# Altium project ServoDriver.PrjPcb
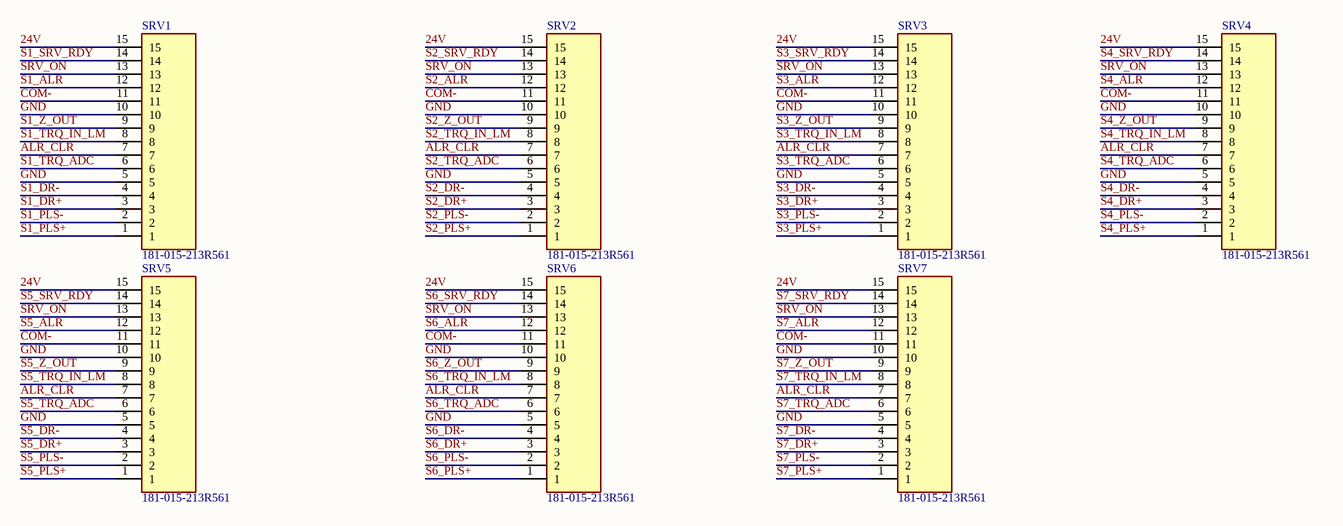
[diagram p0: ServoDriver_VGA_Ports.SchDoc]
1 sheet, 7 parts. Net scope: global (net labels, ports and power ports of the same name join across sheets).
Board file: ServoDriver.PcbDoc

## Sheet ServoDriver_VGA_Ports.SchDoc
size A4

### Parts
SRV1  181-015-213R561  [NORCOMP_181-015-213R561]
SRV2  181-015-213R561  [NORCOMP_181-015-213R561]
SRV3  181-015-213R561  [NORCOMP_181-015-213R561]
SRV4  181-015-213R561  [NORCOMP_181-015-213R561]
SRV5  181-015-213R561  [NORCOMP_181-015-213R561]
SRV6  181-015-213R561  [NORCOMP_181-015-213R561]
SRV7  181-015-213R561  [NORCOMP_181-015-213R561]

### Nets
24V: SRV1.15 SRV2.15 SRV3.15 SRV4.15 SRV5.15 SRV6.15 SRV7.15
ALR_CLR: SRV1.7 SRV2.7 SRV3.7 SRV4.7 SRV5.7 SRV6.7 SRV7.7
COM-: SRV1.11 SRV2.11 SRV3.11 SRV4.11 SRV5.11 SRV6.11 SRV7.11
GND: SRV1.5 SRV1.10 SRV2.5 SRV2.10 SRV3.5 SRV3.10 SRV4.5 SRV4.10 SRV5.5 SRV5.10 SRV6.5 SRV6.10 SRV7.5 SRV7.10
S1_ALR: SRV1.12
S1_DR+: SRV1.3
S1_DR-: SRV1.4
S1_PLS+: SRV1.1
S1_PLS-: SRV1.2
S1_SRV_RDY: SRV1.14
S1_TRQ_ADC: SRV1.6
S1_TRQ_IN_LM: SRV1.8
S1_Z_OUT: SRV1.9
S2_ALR: SRV2.12
S2_DR+: SRV2.3
S2_DR-: SRV2.4
S2_PLS+: SRV2.1
S2_PLS-: SRV2.2
S2_SRV_RDY: SRV2.14
S2_TRQ_ADC: SRV2.6
S2_TRQ_IN_LM: SRV2.8
S2_Z_OUT: SRV2.9
S3_ALR: SRV3.12
S3_DR+: SRV3.3
S3_DR-: SRV3.4
S3_PLS+: SRV3.1
S3_PLS-: SRV3.2
S3_SRV_RDY: SRV3.14
S3_TRQ_ADC: SRV3.6
S3_TRQ_IN_LM: SRV3.8
S3_Z_OUT: SRV3.9
S4_ALR: SRV4.12
S4_DR+: SRV4.3
S4_DR-: SRV4.4
S4_PLS+: SRV4.1
S4_PLS-: SRV4.2
S4_SRV_RDY: SRV4.14
S4_TRQ_ADC: SRV4.6
S4_TRQ_IN_LM: SRV4.8
S4_Z_OUT: SRV4.9
S5_ALR: SRV5.12
S5_DR+: SRV5.3
S5_DR-: SRV5.4
S5_PLS+: SRV5.1
S5_PLS-: SRV5.2
S5_SRV_RDY: SRV5.14
S5_TRQ_ADC: SRV5.6
S5_TRQ_IN_LM: SRV5.8
S5_Z_OUT: SRV5.9
S6_ALR: SRV6.12
S6_DR+: SRV6.3
S6_DR-: SRV6.4
S6_PLS+: SRV6.1
S6_PLS-: SRV6.2
S6_SRV_RDY: SRV6.14
S6_TRQ_ADC: SRV6.6
S6_TRQ_IN_LM: SRV6.8
S6_Z_OUT: SRV6.9
S7_ALR: SRV7.12
S7_DR+: SRV7.3
S7_DR-: SRV7.4
S7_PLS+: SRV7.1
S7_PLS-: SRV7.2
S7_SRV_RDY: SRV7.14
S7_TRQ_ADC: SRV7.6
S7_TRQ_IN_LM: SRV7.8
S7_Z_OUT: SRV7.9
SRV_ON: SRV1.13 SRV2.13 SRV3.13 SRV4.13 SRV5.13 SRV6.13 SRV7.13

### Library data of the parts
SRV1-SRV7 = 181-015-213R561: 15 Position D-Sub, High Density Receptacle, Female Sockets Connector; MF: NorComp Inc.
